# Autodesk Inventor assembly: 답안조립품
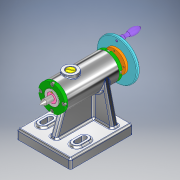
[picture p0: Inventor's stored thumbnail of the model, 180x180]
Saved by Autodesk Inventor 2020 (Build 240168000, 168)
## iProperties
Created: 2021-11
Part Number: 답안조립품
Document SubType Name: Assembly
Designer: user
Author: user
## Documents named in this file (18)
- C:\Users\user\Desktop\711112V1006 (1)\답안조립품.iam
- C:\Users\user\Desktop\711112V1006 (1)\나사.ipt
- C:\Users\user\Desktop\711112V1006 (1)\나사축.ipt
- C:\Users\user\Desktop\711112V1006 (1)\너트 M8.ipt
- C:\Users\user\Desktop\711112V1006 (1)\돌림판.ipt
- C:\Users\user\Desktop\711112V1006 (1)\멈춤나사 M3.ipt
- C:\Users\user\Desktop\711112V1006 (1)\본체.ipt
- C:\Users\user\Desktop\711112V1006 (1)\볼트 M3.ipt
- C:\Users\user\Desktop\711112V1006 (1)\부시.ipt
- C:\Users\user\Desktop\711112V1006 (1)\센터.ipt
- C:\Users\user\Desktop\711112V1006 (1)\센터홀더.ipt
- C:\Users\user\Desktop\711112V1006 (1)\슬리브.ipt
- C:\Users\user\Desktop\711112V1006 (1)\와셔.ipt
- C:\Users\user\Desktop\711112V1006 (1)\중공축.ipt
- C:\Users\user\Desktop\711112V1006 (1)\커버.ipt
- C:\Users\user\Desktop\711112V1006 (1)\키 4 x 4 x 10.ipt
- C:\Users\user\Desktop\711112V1006 (1)\플랜지.ipt
- C:\Users\user\Desktop\711112V1006 (1)\핸들.ipt
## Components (2 placed, 2 different names)
1. 플랜지:1
2. 핸들:1 — 플러쉬:4
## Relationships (1: Flush 1)
- 플러쉬:4 [Flush]: 핸들:1
